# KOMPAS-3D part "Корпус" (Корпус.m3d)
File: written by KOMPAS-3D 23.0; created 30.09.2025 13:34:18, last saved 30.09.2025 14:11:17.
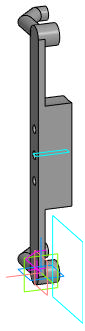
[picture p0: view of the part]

Document properties: Автор: Inspektor_Kot; Полное имя файла: I:\Autodesk Inventor Projects\ИМ-ИТ ЦД\Вариант 5\Корпус.m3d

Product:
- Part/product: Корпус
    Масса: 2.966432
- Part/product: Корпус  | designation 01
    Масса: 2.966432

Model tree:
1. Эскиз:7  (with: Элемент вращения:1)
2. Элемент выдавливания:3
     Расстояние 2 = 22
3. Эскиз:8  (with: Элемент выдавливания:3)
4. Элемент выдавливания:4
     Расстояние 1 = 10
5. Средняя плоскость:2  (with: Элемент вращения:1)
6. Эскиз:9  (with: Элемент выдавливания:4)
7. Элемент выдавливания:5  (with: Элемент выдавливания:3)
     Расстояние 1 = 22
8. Эскиз:10  (with: Элемент выдавливания:4, Элемент выдавливания:5)
9. Элемент выдавливания:6
     Расстояние 1 = 40
10. Эскиз:12  (with: Элемент выдавливания:4)
11. Эскиз:13  (with: Элемент выдавливания:4, Элемент вращения:2)
12. Элемент по траектории:1
13. Эскиз:14  (with: Элемент выдавливания:6)
14. Элемент выдавливания:7
15. Нормальная плоскость:2  (with: Элемент выдавливания:7)
16. Зеркальное отражение:1
17. Экземпляр ( 1 )
18. Экземпляр ( 2 )
19. Тело 2

Referenced files in I:\Autodesk Inventor Projects\ИМ-ИТ ЦД\Вариант 5\: Гироскутер.a3d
